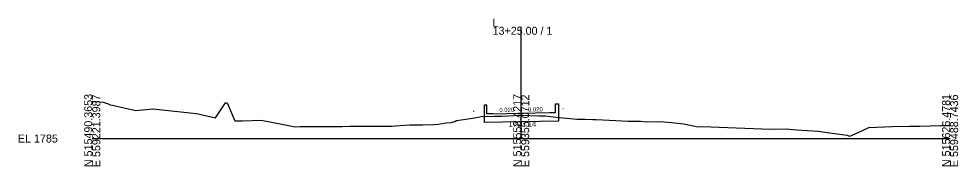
# Model space of a CAD drawing. Extents: x -26 to 1303, y -10 to 9545.
# Drawn here: x -25.7 to 302.8, y 8990.3 to 9041.9 of the extents above; entities that cross this region are included whole.
import ezdxf

# ---------------------------------------------------------------- set-up
doc = ezdxf.new("R2010")
doc.units = 0
for name, color, linetype in [('Exist Cross Section Cell', 7, 'Continuous'), ('Exist XS Center Line Elevation Label', 7, 'Continuous'), ('Exist XS Ground Line', 7, 'Continuous'), ('Prop XS Bridge', 7, 'Continuous'), ('Prop XS Dump Level', 7, 'Continuous'), ('Prop XS Guardrail', 7, 'Continuous'), ('Prop XS SE Text', 7, 'Continuous')]:
    doc.layers.add(name, color=color, linetype=linetype)

msp = doc.modelspace()

# ---------------------------------------------------------------- linework, layer by layer
at = {"layer": 'Exist Cross Section Cell'}
for p, q in [((150, 9000), (150, 9039.12)), ((0, 9000), (150, 9000)), ((150, 9000), (300, 9000))]:
    msp.add_line(p, q, dxfattribs=at)
at = {"layer": 'Exist XS Ground Line'}
for p, q in [((0, 9013.04), (3.77, 9012.7)), ((3.77, 9012.7), (4.91, 9012.38)), ((4.91, 9012.38), (5.37, 9012.22)), ((5.37, 9012.22), (6.21, 9011.76)), ((6.21, 9011.76), (7.09, 9011.68)), ((7.09, 9011.68), (15.19, 9009.79)), ((43.09, 9007.25), (46.55, 9012.53)), ((46.55, 9012.53), (47.18, 9012.49)), ((47.18, 9012.49), (49.9, 9006.24)), ((15.19, 9009.79), (21.21, 9010.45)), ((21.21, 9010.45), (34.23, 9009.02)), ((34.23, 9009.02), (36.43, 9008.82)), ((36.43, 9008.82), (43.09, 9007.25)), ((49.9, 9006.24), (52.39, 9006.22)), ((52.39, 9006.22), (59.07, 9006.41)), ((59.07, 9006.41), (66.83, 9004.88)), ((121.09, 9005.05), (122.35, 9005.21)), ((122.35, 9005.21), (123.72, 9005.49)), ((123.72, 9005.49), (125.56, 9005.64)), ((125.56, 9005.64), (126.78, 9006)), ((126.78, 9006), (127.37, 9006.29)), ((127.37, 9006.29), (133.82, 9007.27)), ((133.82, 9007.27), (134.27, 9007.34)), ((134.27, 9007.34), (135.59, 9007.63)), ((135.59, 9007.63), (135.97, 9007.66)), ((135.97, 9007.66), (140.68, 9007.8)), ((140.68, 9007.8), (143.09, 9007.86)), ((143.09, 9007.86), (149.91, 9008.15)), ((149.91, 9008.15), (156.24, 9007.99)), ((156.24, 9007.99), (158.52, 9007.92)), ((158.52, 9007.92), (161.23, 9007.62)), ((161.23, 9007.62), (163.41, 9007.39)), ((163.41, 9007.39), (169.48, 9006.81)), ((169.48, 9006.81), (172.34, 9006.83)), ((172.34, 9006.83), (175.01, 9006.64)), ((175.01, 9006.64), (176.21, 9006.64)), ((176.21, 9006.64), (183.09, 9006.26)), ((183.09, 9006.26), (187.44, 9006.07)), ((187.44, 9006.07), (191.71, 9006.02)), ((191.71, 9006.02), (193.91, 9005.89)), ((193.91, 9005.89), (198.55, 9006)), ((198.55, 9006), (202.6, 9005.61)), ((202.6, 9005.61), (206.75, 9005.14)), ((206.75, 9005.14), (211.94, 9004.12)), ((66.83, 9004.88), (70.94, 9004.14)), ((70.94, 9004.14), (72.7, 9004.19)), ((72.7, 9004.19), (73.82, 9004.16)), ((73.82, 9004.16), (77.98, 9004.25)), ((77.98, 9004.25), (80.37, 9004.23)), ((80.37, 9004.23), (85.73, 9004.23)), ((85.73, 9004.23), (87.43, 9004.22)), ((87.43, 9004.22), (90.14, 9004.34)), ((90.14, 9004.34), (92.12, 9004.32)), ((92.12, 9004.32), (93.16, 9004.3)), ((93.16, 9004.3), (95.75, 9004.28)), ((95.75, 9004.28), (103.15, 9004.35)), ((103.15, 9004.35), (104.32, 9004.35)), ((104.32, 9004.35), (104.94, 9004.33)), ((104.94, 9004.33), (105.93, 9004.45)), ((105.93, 9004.45), (111.01, 9004.75)), ((111.01, 9004.75), (111.74, 9004.77)), ((111.74, 9004.77), (113.48, 9004.74)), ((113.48, 9004.74), (115.56, 9004.74)), ((115.56, 9004.74), (119.33, 9004.87)), ((119.33, 9004.87), (121.09, 9005.05)), ((211.94, 9004.12), (213.31, 9004.17)), ((213.31, 9004.17), (237.16, 9003.25)), ((237.16, 9003.25), (242.71, 9003.41)), ((242.71, 9003.41), (246.31, 9003.1)), ((246.31, 9003.1), (254.02, 9002.54)), ((254.02, 9002.54), (257.8, 9001.96)), ((257.8, 9001.96), (263.99, 9001.19)), ((264.92, 9000.85), (267.87, 9002.09)), ((267.87, 9002.09), (271.63, 9003.91)), ((271.63, 9003.91), (279.71, 9004.18)), ((279.71, 9004.18), (285.79, 9004.28)), ((285.79, 9004.28), (289.46, 9004.27)), ((289.46, 9004.27), (296.7, 9004.54)), ((296.7, 9004.54), (300, 9004.59)), ((263.99, 9001.19), (264.44, 9000.89)), ((264.44, 9000.89), (264.92, 9000.85))]:
    msp.add_line(p, q, dxfattribs=at)
at = {"layer": 'Prop XS Bridge'}
for p, q in [((162, 9009.11), (162, 9012.11)), ((162, 9012.11), (163, 9012.11)), ((163, 9012.11), (163, 9009.11)), ((137, 9011.63), (137, 9008.63)), ((138, 9011.63), (137, 9011.63)), ((137, 9008.63), (137, 9005.63)), ((138, 9008.63), (138, 9011.63)), ((140, 9008.67), (138, 9008.63)), ((140, 9008.67), (150, 9008.87)), ((150, 9008.87), (160, 9009.07)), ((160, 9009.07), (162, 9009.11)), ((163, 9009.11), (163, 9006.11)), ((163, 9006.11), (137, 9005.63))]:
    msp.add_line(p, q, dxfattribs=at)
at = {"layer": 'Prop XS Guardrail'}
for p, q in [((133.46, 9009.62), (133.17, 9009.42)), ((164.6, 9010.46), (164.63, 9010.4))]:
    msp.add_line(p, q, dxfattribs=at)

# ---------------------------------------------------------------- texts
at = {"layer": 'Exist Cross Section Cell'}
for s, p in [('L', (140, 9039.12)), ('13+25.00 / 1', (140, 9036.32)), ('EL 1785', (-26, 8998.6))]:
    msp.add_text(s, height=2.8, dxfattribs=at).set_placement(p)
for s, p in [('N 515490.3653', (0, 8990)), ('E 559221.3987', (2.8, 8990)), ('N 515558.4217', (150, 8990)), ('E 559355.0712', (152.8, 8990)), ('N 515626.4781', (300, 8990)), ('E 559488.7436', (302.8, 8990))]:
    msp.add_text(s, height=2.8, rotation=90, dxfattribs=at).set_placement(p)
at = {"layer": 'Exist XS Center Line Elevation Label'}
msp.add_text('1793.14', height=2, dxfattribs=at).set_placement((145.59, 9004.14))
at = {"layer": 'Prop XS Dump Level'}
for s, height, p in [('Case1', 0.04, (163, 9008.91)), ('Case1', 0.04, (163, 9008.9)), ('Eop', 0.3, (130, 9006.39)), ('Eop', 0.3, (170, 9006.52))]:
    msp.add_text(s, height=height, dxfattribs=at).set_placement(p)
at = {"layer": 'Prop XS SE Text'}
for p in [(142.38, 9009.21), (152.38, 9009.41)]:
    msp.add_text('0.020', height=1.5, rotation=1.1458, dxfattribs=at).set_placement(p)

doc.saveas('drawing.dxf')
